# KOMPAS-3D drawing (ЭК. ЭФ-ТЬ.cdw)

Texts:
  ДП.11.213.06.000.00.ТБ
  Телятник на 120 голов в СПК колхоз "Дзержинского" Даниловского МР Ярославской обл.
  Факт
  Проект
  Показатели
  1  Капитальные вложения, тыс.руб.
  2  Среднегодовое поголовье телят, гол.
  3  Среднесуточный прирост, г.
  4  Производственные затраты, тыс.руб.
  В том числе:       затраты на корма
  амортизация
  затраты на ТО и ТР
  5  Себестоимость 1 центнера прироста,
  руб.
  6.1  На 1 центнер прироста
  6.2  На весь объём прироста
  7  Абсолютный коэффициент
  эффективности
  Телятник на 120 голов
  в СПК колхоз "Дзержинского"
  Даниловского МР Ярославской обл.
  Разраб.
  Куракин
  Пров.
  Шмигель
  Королёва
  Утв.
  Орлов
  ФГОУ ВПО ЯГСХА
  ДП.09.511.07Д3-
  Экономическая эффективность реконст-
  рукции полов в телятнике на 120 голов.
Dimensions and other numbers on the sheet: 2010 г.; 296820,1; 120; 570; 609,9; 7099; 4894,9; 6  Экономия затрат, руб.; 8  Срок окупаемости, лет; 4363; 3054,1; 608; 615,4; 393; 400,4; 5042; 9222; 3279,1; 875966,31; 2,95; 0,33; 1; 0; 2; 3; 4; 5; 6; 7; 8; 9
